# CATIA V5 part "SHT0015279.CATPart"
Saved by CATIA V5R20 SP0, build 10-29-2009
Part number: Part98
Source: Unknown
Bounding box of the stored display mesh (mm): x -565 to 0, y -745.013 to 0, z 0 to 1054.9
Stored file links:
  E:\吉利商用车G3\10 2D\钣金单件图纸\SHT0015279-标配底支架左边板\SHT0015279.CATPart
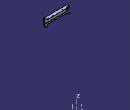
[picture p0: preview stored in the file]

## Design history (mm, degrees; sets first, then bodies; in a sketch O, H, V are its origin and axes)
Set1
  AxisSystem1 "AXIS2_PLACEMENT_3D #6391": origin (0, 0, 0), X (1, 0, 0), Y (0, 1, 0), Z (0, 0, 1)
Body1 "几何体.75" (main body)
Body2 "几何体.76"
  Solid1: solid without history
  RemoveFace1: RemoveFaces (face of Solid1; face of Solid1)
  Thickness1: Thickness -0.5, Face (face of Solid1; face of Solid1; face of Solid1; face of Solid1)
  Body3 "2023.2.10加定位孔"
    Solid2: solid without history
  Remove1: tool Body3
  Sketch1 on face of Solid1, origin (0, -745.0131, 0), H (1, 0, 0), V (0, 0, 1)
    line L1 (-518.6302, 1036.997) -> (-155.1614, 1036.997)
    line L2 (-155.1614, 1036.997) -> (-155.1614, 964.4797)
    line L3 (-155.1614, 964.4797) -> (-518.6302, 964.4797)
    line L4 (-518.6302, 964.4797) -> (-518.6302, 1036.997)
    horizontal: L1 H, L3 H
    vertical: L2 V, L4 V
  Pad1: profile Sketch1, direction (0, 1, 0), length 2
